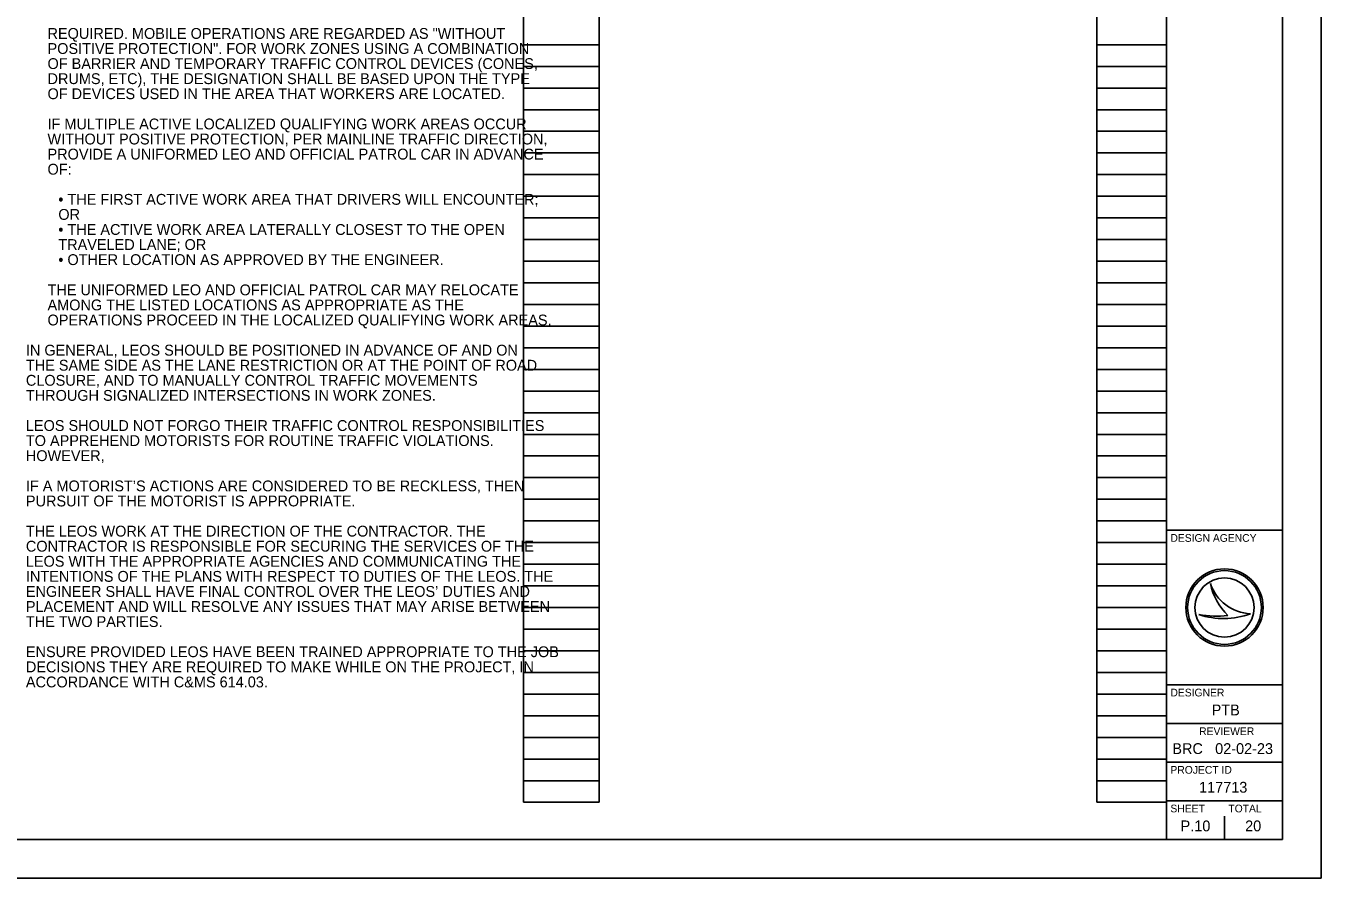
# Model space of a CAD drawing. Extents: x 0 to 34, y 0 to 22.
# Drawn here: x 17.24 to 34, y 0 to 11.02 of the extents above; entities that cross this region are included whole.
import ezdxf

# ---------------------------------------------------------------- set-up
doc = ezdxf.new("R2010")
doc.units = 0
for name, color, linetype in [('SH_Border', 7, 'Continuous'), ('SH_Cut_Line', 7, 'Continuous'), ('SH_Data', 7, 'Continuous'), ('SH_Text', 7, 'Continuous')]:
    doc.layers.add(name, color=color, linetype=linetype)

msp = doc.modelspace()

# ---------------------------------------------------------------- linework, layer by layer
at = {"layer": 'SH_Border'}
for p, q in [((32, 0.5), (32, 21.5)), ((32, 4.5), (33.5, 4.5)), ((32, 2.5), (33.5, 2.5)), ((32, 2), (33.5, 2)), ((32, 1.5), (33.5, 1.5)), ((32, 1), (33.5, 1))]:
    msp.add_line(p, q, dxfattribs=at)
msp.add_lwpolyline([(1.5, 21.5), (33.5, 21.5), (33.5, 0.5), (1.5, 0.5)], close=True, dxfattribs=at)
at = {"layer": 'SH_Cut_Line'}
msp.add_lwpolyline([(0, 0), (34, 0), (34, 22), (0, 22)], close=True, dxfattribs=at)
at = {"layer": 'SH_Data'}
for p, q in [((23.68, 0.98), (23.68, 21.14)), ((24.66, 0.98), (24.66, 21.14)), ((31.1, 0.98), (31.1, 21.14)), ((32, 0.98), (32, 21.14)), ((23.68, 10.78), (24.66, 10.78)), ((31.1, 10.78), (32, 10.78)), ((23.68, 10.5), (24.66, 10.5)), ((31.1, 10.5), (32, 10.5)), ((23.68, 10.22), (24.66, 10.22)), ((31.1, 10.22), (32, 10.22)), ((23.68, 9.94), (24.66, 9.94)), ((31.1, 9.94), (32, 9.94)), ((23.68, 9.66), (24.66, 9.66)), ((31.1, 9.66), (32, 9.66)), ((23.68, 9.38), (24.66, 9.38)), ((31.1, 9.38), (32, 9.38)), ((23.68, 9.1), (24.66, 9.1)), ((31.1, 9.1), (32, 9.1)), ((23.68, 8.82), (24.66, 8.82)), ((31.1, 8.82), (32, 8.82)), ((23.68, 8.54), (24.66, 8.54)), ((31.1, 8.54), (32, 8.54)), ((23.68, 8.26), (24.66, 8.26)), ((31.1, 8.26), (32, 8.26)), ((23.68, 7.98), (24.66, 7.98)), ((31.1, 7.98), (32, 7.98)), ((23.68, 7.7), (24.66, 7.7)), ((31.1, 7.7), (32, 7.7)), ((23.68, 7.42), (24.66, 7.42)), ((31.1, 7.42), (32, 7.42)), ((23.68, 7.14), (24.66, 7.14)), ((31.1, 7.14), (32, 7.14)), ((23.68, 6.86), (24.66, 6.86)), ((31.1, 6.86), (32, 6.86)), ((23.68, 6.58), (24.66, 6.58)), ((31.1, 6.58), (32, 6.58)), ((23.68, 6.3), (24.66, 6.3)), ((31.1, 6.3), (32, 6.3)), ((23.68, 6.02), (24.66, 6.02)), ((31.1, 6.02), (32, 6.02)), ((23.68, 5.74), (24.66, 5.74)), ((31.1, 5.74), (32, 5.74)), ((23.68, 5.46), (24.66, 5.46)), ((31.1, 5.46), (32, 5.46)), ((23.68, 5.18), (24.66, 5.18)), ((31.1, 5.18), (32, 5.18)), ((23.68, 4.9), (24.66, 4.9)), ((31.1, 4.9), (32, 4.9)), ((23.68, 4.62), (24.66, 4.62)), ((31.1, 4.62), (32, 4.62)), ((23.68, 4.34), (24.66, 4.34)), ((31.1, 4.34), (32, 4.34)), ((23.68, 4.06), (24.66, 4.06)), ((31.1, 4.06), (32, 4.06)), ((23.68, 3.78), (24.66, 3.78)), ((31.1, 3.78), (32, 3.78)), ((32.567, 3.81), (32.567, 3.81)), ((23.68, 3.5), (24.66, 3.5)), ((31.1, 3.5), (32, 3.5)), ((32.417, 3.41), (32.417, 3.41)), ((32.75, 3.5), (32.75, 3.5)), ((33.087, 3.419), (33.087, 3.419)), ((23.68, 3.22), (24.66, 3.22)), ((31.1, 3.22), (32, 3.22)), ((23.68, 2.94), (24.66, 2.94)), ((31.1, 2.94), (32, 2.94)), ((23.68, 2.66), (24.66, 2.66)), ((31.1, 2.66), (32, 2.66)), ((23.68, 2.38), (24.66, 2.38)), ((31.1, 2.38), (32, 2.38)), ((23.68, 2.1), (24.66, 2.1)), ((31.1, 2.1), (32, 2.1)), ((23.68, 1.82), (24.66, 1.82)), ((31.1, 1.82), (32, 1.82)), ((23.68, 1.54), (24.66, 1.54)), ((31.1, 1.54), (32, 1.54)), ((23.68, 1.26), (24.66, 1.26)), ((31.1, 1.26), (32, 1.26)), ((23.68, 0.98), (24.66, 0.98)), ((31.1, 0.98), (32, 0.98)), ((32.375, 0.675), (32.375, 0.675)), ((32.75, 0.5), (32.75, 0.8))]:
    msp.add_line(p, q, dxfattribs=at)
for radius in [0.5, 0.477, 0.477, 0.382]:
    msp.add_circle((32.75, 3.5), radius, dxfattribs=at)
for centre, radius, start, end in [((33.116, 3.998), 0.58, 198.9257, 198.9319), ((33.347, 3.97), 0.796, 191.6379, 191.6421), ((33.116, 3.998), 0.58, 198.9319, 267.1657), ((33.347, 3.97), 0.796, 191.6421, 226.0947), ((32.739, 4.37), 1.013, 251.4576, 290.0832), ((32.648, 4.654), 1.266, 259.4964, 259.4995), ((32.739, 4.37), 1.013, 251.4527, 251.4576), ((32.648, 4.654), 1.266, 259.4995, 276.6672)]:
    msp.add_arc(centre, radius, start, end, dxfattribs=at)

# ---------------------------------------------------------------- texts
for s, height, p in [('DESIGN AGENCY', 0.1, (32.05, 4.35)), ('DESIGNER', 0.1, (32.05, 2.35)), ('PTB', 0.14, (32.584, 2.105)), ('REVIEWER', 0.1, (32.422, 1.85)), ('BRC', 0.14, (32.075, 1.605)), ('02-02-23', 0.14, (32.629, 1.605)), ('PROJECT ID', 0.1, (32.05, 1.35)), ('117713', 0.14, (32.421, 1.105)), ('SHEET', 0.1, (32.05, 0.85)), ('TOTAL', 0.1, (32.8, 0.85)), ('P.10', 0.14, (32.182, 0.605)), ('20', 0.14, (33.017, 0.605))]:
    msp.add_text(s, height=height, dxfattribs=at).set_placement(p)
at = {"layer": 'SH_Text'}
for s, p in [('REQUIRED. MOBILE OPERATIONS ARE REGARDED AS "WITHOUT ', (17.52, 10.856)), ('POSITIVE PROTECTION". FOR WORK ZONES USING A COMBINATION ', (17.52, 10.661)), ('OF BARRIER AND TEMPORARY TRAFFIC CONTROL DEVICES (CONES, ', (17.52, 10.466)), ('DRUMS, ETC), THE DESIGNATION SHALL BE BASED UPON THE TYPE ', (17.52, 10.271)), ('OF DEVICES USED IN THE AREA THAT WORKERS ARE LOCATED.', (17.52, 10.076)), ('IF MULTIPLE ACTIVE LOCALIZED QUALIFYING WORK AREAS OCCUR', (17.52, 9.685)), ('WITHOUT POSITIVE PROTECTION, PER MAINLINE TRAFFIC DIRECTION, ', (17.52, 9.49)), ('PROVIDE A UNIFORMED LEO AND OFFICIAL PATROL CAR IN ADVANCE ', (17.52, 9.295)), ('OF:', (17.52, 9.1)), ('• THE FIRST ACTIVE WORK AREA THAT DRIVERS WILL ENCOUNTER; ', (17.66, 8.71)), ('OR', (17.66, 8.515)), ('• THE ACTIVE WORK AREA LATERALLY CLOSEST TO THE OPEN ', (17.66, 8.32)), ('TRAVELED LANE; OR', (17.66, 8.125)), ('• OTHER LOCATION AS APPROVED BY THE ENGINEER.', (17.66, 7.93)), ('THE UNIFORMED LEO AND OFFICIAL PATROL CAR MAY RELOCATE ', (17.52, 7.539)), ('AMONG THE LISTED LOCATIONS AS APPROPRIATE AS THE ', (17.52, 7.344)), ('OPERATIONS PROCEED IN THE LOCALIZED QUALIFYING WORK AREAS.', (17.52, 7.149)), ('IN GENERAL, LEOS SHOULD BE POSITIONED IN ADVANCE OF AND ON ', (17.24, 6.759)), ('THE SAME SIDE AS THE LANE RESTRICTION OR AT THE POINT OF ROAD ', (17.24, 6.564)), ('CLOSURE, AND TO MANUALLY CONTROL TRAFFIC MOVEMENTS ', (17.24, 6.369)), ('THROUGH SIGNALIZED INTERSECTIONS IN WORK ZONES. ', (17.24, 6.174)), ('LEOS SHOULD NOT FORGO THEIR TRAFFIC CONTROL RESPONSIBILITIES ', (17.24, 5.784)), ('TO APPREHEND MOTORISTS FOR ROUTINE TRAFFIC VIOLATIONS. ', (17.24, 5.589)), ('HOWEVER, ', (17.24, 5.394)), ('IF A MOTORIST’S ACTIONS ARE CONSIDERED TO BE RECKLESS, THEN ', (17.24, 5.003)), ('PURSUIT OF THE MOTORIST IS APPROPRIATE. ', (17.24, 4.808)), ('THE LEOS WORK AT THE DIRECTION OF THE CONTRACTOR. THE ', (17.24, 4.418)), ('CONTRACTOR IS RESPONSIBLE FOR SECURING THE SERVICES OF THE ', (17.24, 4.223)), ('LEOS WITH THE APPROPRIATE AGENCIES AND COMMUNICATING THE ', (17.24, 4.028)), ('INTENTIONS OF THE PLANS WITH RESPECT TO DUTIES OF THE LEOS. THE ', (17.24, 3.833)), ('ENGINEER SHALL HAVE FINAL CONTROL OVER THE LEOS’ DUTIES AND ', (17.24, 3.638)), ('PLACEMENT AND WILL RESOLVE ANY ISSUES THAT MAY ARISE BETWEEN ', (17.24, 3.443)), ('THE TWO PARTIES.', (17.24, 3.248)), ('ENSURE PROVIDED LEOS HAVE BEEN TRAINED APPROPRIATE TO THE JOB ', (17.24, 2.858)), ('DECISIONS THEY ARE REQUIRED TO MAKE WHILE ON THE PROJECT, IN ', (17.24, 2.662)), ('ACCORDANCE WITH C&MS 614.03.', (17.24, 2.467))]:
    msp.add_text(s, height=0.14, dxfattribs=at).set_placement(p)

doc.saveas('drawing.dxf')
